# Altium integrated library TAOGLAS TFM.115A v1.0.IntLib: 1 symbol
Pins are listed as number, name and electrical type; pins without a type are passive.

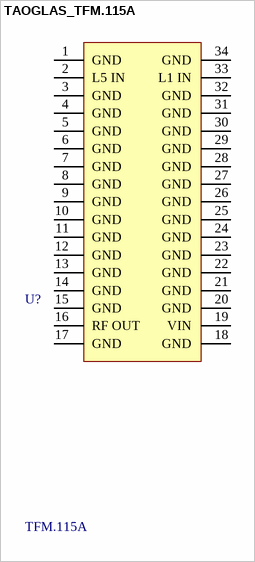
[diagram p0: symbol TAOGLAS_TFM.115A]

## TAOGLAS_TFM.115A
designator U?, comment TFM.115A
GNSS Front End Module for Bands L1, B1, G1, L Band and L5; MFG: Taoglas; Temp_High: +85C; Temp_Low: -40C; ComponentLibStatus: Created
footprint TAOGLAS_TFM.115A (GNSS Front End Module for Bands L1, B1, G1, L Band and L5)
pins: 1 GND, 2 L5 IN, 3 GND, 4 GND, 5 GND, 6 GND, 7 GND, 8 GND, 9 GND, 10 GND, 11 GND, 12 GND, 13 GND, 14 GND, 15 GND, 16 RF OUT, 17 GND, 18 GND, 19 VIN, 20 GND, 21 GND, 22 GND, 23 GND, 24 GND, 25 GND, 26 GND, 27 GND, 28 GND, 29 GND, 30 GND, 31 GND, 32 GND, 33 L1 IN, 34 GND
